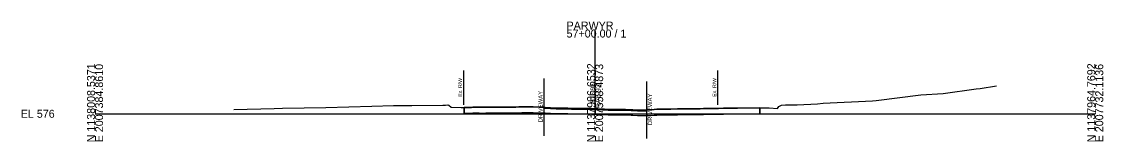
# Model space of a CAD drawing. Extents: x -2173 to 2007764, y -181 to 1138563.
# Drawn here: x 1017.4 to 1395.9, y 2490.3 to 2532.3 of the extents above; entities that cross this region are included whole.
import ezdxf

# ---------------------------------------------------------------- set-up
doc = ezdxf.new("R2010")
doc.units = 0
for name, color, linetype in [('Default', 7, 'Continuous'), ('RD_PD_Final_TrvlWay', 7, 'Continuous'), ('RD_PD_MedBWall', 7, 'Continuous'), ('RD_XS_ExPaveRet', 7, 'Continuous'), ('RD_XS_ExRW', 7, 'Continuous'), ('RD_XS_MedBWall', 7, 'Continuous'), ('RD_XS_SideStreet', 7, 'Continuous'), ('RD_XS_TX_Elev_EX', 7, 'Continuous'), ('RD_XS_TX_Elev_PR', 7, 'Continuous')]:
    doc.layers.add(name, color=color, linetype=linetype)

msp = doc.modelspace()

# ---------------------------------------------------------------- linework, layer by layer
at = {"layer": 'RD_PD_Final_TrvlWay'}
msp.add_lwpolyline([(1091.67, 2501.5), (1105.81, 2501.9), (1108.66, 2501.96), (1123.82, 2502.19), (1139.92, 2502.72), (1147.5, 2502.88), (1153.91, 2502.91), (1164.83, 2503.03), (1165.78, 2503.04), (1166.6, 2503.08), (1166.9, 2503.06), (1167.68, 2502.26), (1171.16, 2502.22), (1172.25, 2502.17), (1174.88, 2502.25), (1175.29, 2502.29), (1176.29, 2502.31), (1177.57, 2502.28), (1178.3, 2502.27), (1179.88, 2502.3), (1180.32, 2502.3), (1182.33, 2502.35), (1183.34, 2502.35), (1184.49, 2502.34), (1186.36, 2502.33), (1186.8, 2502.32), (1188.38, 2502.31), (1189.11, 2502.32), (1190.4, 2502.37), (1191.41, 2502.38), (1192.41, 2502.39), (1193.72, 2502.4), (1194.43, 2502.41), (1196.03, 2502.39), (1196.44, 2502.39), (1198.46, 2502.34), (1199.33, 2502.33), (1200.64, 2502.31), (1202.49, 2502.16), (1202.95, 2502.14), (1204.51, 2502.08), (1205.25, 2502.09), (1206.52, 2502.09), (1207.56, 2502.08), (1208.54, 2502.05), (1209.87, 2501.99), (1210.55, 2501.96), (1212.17, 2501.95), (1212.57, 2501.95), (1214.59, 2501.98), (1215.33, 2501.96), (1216.79, 2501.92), (1218.1, 2501.87), (1218.62, 2501.85), (1219.09, 2501.83), (1220.63, 2501.75), (1221.4, 2501.7), (1222.65, 2501.64), (1223.71, 2501.62), (1224.67, 2501.58), (1226.01, 2501.58), (1226.68, 2501.59), (1228.32, 2501.58), (1228.7, 2501.58), (1230.71, 2501.52), (1231.32, 2501.49), (1232.93, 2501.41), (1234.74, 2501.36), (1235.24, 2501.37), (1236.76, 2501.35), (1237.54, 2501.41), (1238.78, 2501.53), (1239.73, 2501.57), (1240.79, 2501.6), (1241.52, 2501.62), (1242.81, 2501.61), (1244.03, 2501.63), (1244.54, 2501.65), (1246.89, 2501.68), (1247.31, 2501.69), (1249.08, 2501.74), (1250.87, 2501.73), (1252.65, 2501.76), (1254.9, 2501.76), (1256, 2501.8), (1256.92, 2501.82), (1257.62, 2501.84), (1258.73, 2501.86), (1260.62, 2501.87), (1261.21, 2501.88), (1263, 2501.92), (1263.31, 2501.93), (1265.22, 2501.99), (1267, 2502.01), (1267.93, 2502.02), (1275.75, 2502.05), (1276.21, 2502.04), (1278.97, 2502.03), (1281.87, 2501.87), (1282.36, 2502.56), (1283.3, 2503.03), (1284.76, 2503.08), (1285.52, 2503.11), (1287.92, 2503.08), (1288.74, 2503.13), (1295.93, 2503.48), (1297.93, 2503.72), (1315.18, 2504.5), (1316.38, 2504.62), (1332.12, 2506.64), (1339.87, 2507.08), (1351.46, 2508.71), (1352.88, 2508.91), (1358.58, 2509.84)], dxfattribs=at)
at = {"layer": 'RD_PD_MedBWall'}
for p, q in [((1218.1, 2500), (1218.1, 2529.53)), ((1043.1, 2500), (1218.1, 2500)), ((1218.1, 2500), (1393.1, 2500))]:
    msp.add_line(p, q, dxfattribs=at)
at = {"layer": 'RD_XS_ExPaveRet'}
for p, q in [((1172.25, 2500.17), (1172.25, 2502.17)), ((1172.25, 2502.17), (1172.25, 2500.17)), ((1200.1, 2502.32), (1199.33, 2502.33)), ((1200.1, 2501.98), (1200.1, 2502.32)), ((1172.25, 2500.17), (1174.88, 2500.25)), ((1172.25, 2500.17), (1174.88, 2500.25)), ((1174.88, 2500.25), (1175.29, 2500.29)), ((1174.88, 2500.25), (1175.29, 2500.29)), ((1175.29, 2500.29), (1176.29, 2500.31)), ((1175.29, 2500.29), (1176.29, 2500.31)), ((1176.29, 2500.31), (1177.57, 2500.28)), ((1176.29, 2500.31), (1177.57, 2500.28)), ((1177.57, 2500.28), (1178.3, 2500.27)), ((1177.57, 2500.28), (1178.3, 2500.27)), ((1178.3, 2500.27), (1179.88, 2500.3)), ((1178.3, 2500.27), (1179.88, 2500.3)), ((1179.88, 2500.3), (1180.32, 2500.3)), ((1179.88, 2500.3), (1180.32, 2500.3)), ((1180.32, 2500.3), (1182.33, 2500.35)), ((1180.32, 2500.3), (1182.33, 2500.35)), ((1182.33, 2500.35), (1183.34, 2500.35)), ((1182.33, 2500.35), (1183.34, 2500.35)), ((1183.34, 2500.35), (1184.49, 2500.34)), ((1183.34, 2500.35), (1184.49, 2500.34)), ((1184.49, 2500.34), (1186.36, 2500.33)), ((1184.49, 2500.34), (1186.36, 2500.33)), ((1186.36, 2500.33), (1186.8, 2500.32)), ((1186.36, 2500.33), (1186.8, 2500.32)), ((1186.8, 2500.32), (1188.38, 2500.31)), ((1186.8, 2500.32), (1188.38, 2500.31)), ((1188.38, 2500.31), (1189.11, 2500.32)), ((1188.38, 2500.31), (1189.11, 2500.32)), ((1189.11, 2500.32), (1190.4, 2500.37)), ((1189.11, 2500.32), (1190.4, 2500.37)), ((1190.4, 2500.37), (1191.41, 2500.38)), ((1190.4, 2500.37), (1191.41, 2500.38)), ((1191.41, 2500.38), (1192.41, 2500.39)), ((1191.41, 2500.38), (1192.41, 2500.39)), ((1192.41, 2500.39), (1193.72, 2500.4)), ((1192.41, 2500.39), (1193.72, 2500.4)), ((1193.72, 2500.4), (1194.43, 2500.41)), ((1193.72, 2500.4), (1194.43, 2500.41)), ((1194.43, 2500.41), (1196.03, 2500.39)), ((1194.43, 2500.41), (1196.03, 2500.39)), ((1196.03, 2500.39), (1196.44, 2500.39)), ((1196.03, 2500.39), (1196.44, 2500.39)), ((1196.44, 2500.39), (1198.46, 2500.34)), ((1196.44, 2500.39), (1198.46, 2500.34)), ((1198.46, 2500.34), (1199.33, 2500.33)), ((1198.46, 2500.34), (1199.33, 2500.33)), ((1199.33, 2500.33), (1200.64, 2500.31)), ((1199.33, 2500.33), (1200.64, 2500.31)), ((1200.64, 2500.31), (1202.49, 2500.16)), ((1200.64, 2500.31), (1202.49, 2500.16)), ((1202.49, 2500.16), (1202.95, 2500.14)), ((1202.49, 2500.16), (1202.95, 2500.14)), ((1202.95, 2500.14), (1204.51, 2500.08)), ((1202.95, 2500.14), (1204.51, 2500.08)), ((1204.51, 2500.08), (1205.25, 2500.09)), ((1204.51, 2500.08), (1205.25, 2500.09)), ((1205.25, 2500.09), (1206.52, 2500.09)), ((1205.25, 2500.09), (1206.52, 2500.09)), ((1206.52, 2500.09), (1207.56, 2500.08)), ((1206.52, 2500.09), (1207.56, 2500.08)), ((1207.56, 2500.08), (1208.54, 2500.05)), ((1207.56, 2500.08), (1208.54, 2500.05)), ((1208.54, 2500.05), (1209.87, 2499.99)), ((1208.54, 2500.05), (1209.87, 2499.99)), ((1209.87, 2499.99), (1210.55, 2499.96)), ((1209.87, 2499.99), (1210.55, 2499.96)), ((1210.55, 2499.96), (1212.17, 2499.95)), ((1210.55, 2499.96), (1212.17, 2499.95)), ((1212.17, 2499.95), (1212.57, 2499.95)), ((1212.17, 2499.95), (1212.57, 2499.95)), ((1212.57, 2499.95), (1214.59, 2499.98)), ((1212.57, 2499.95), (1214.59, 2499.98)), ((1214.59, 2499.98), (1215.33, 2499.96)), ((1214.59, 2499.98), (1215.33, 2499.96)), ((1215.33, 2499.96), (1216.79, 2499.92)), ((1215.33, 2499.96), (1216.79, 2499.92)), ((1216.79, 2499.92), (1218.1, 2499.87)), ((1216.79, 2499.92), (1218.1, 2499.87)), ((1218.1, 2499.87), (1218.62, 2499.85)), ((1218.1, 2499.87), (1218.62, 2499.85)), ((1218.62, 2499.85), (1219.09, 2499.83)), ((1218.62, 2499.85), (1219.09, 2499.83)), ((1219.09, 2499.83), (1220.63, 2499.75)), ((1219.09, 2499.83), (1220.63, 2499.75)), ((1220.63, 2499.75), (1221.4, 2499.7)), ((1220.63, 2499.75), (1221.4, 2499.7)), ((1221.4, 2499.7), (1222.65, 2499.64)), ((1221.4, 2499.7), (1222.65, 2499.64)), ((1222.65, 2499.64), (1223.71, 2499.62)), ((1222.65, 2499.64), (1223.71, 2499.62)), ((1223.71, 2499.62), (1224.67, 2499.58)), ((1223.71, 2499.62), (1224.67, 2499.58)), ((1224.67, 2499.58), (1226.01, 2499.58)), ((1224.67, 2499.58), (1226.01, 2499.58)), ((1226.01, 2499.58), (1226.68, 2499.59)), ((1226.01, 2499.58), (1226.68, 2499.59)), ((1226.68, 2499.59), (1228.32, 2499.58)), ((1226.68, 2499.59), (1228.32, 2499.58)), ((1228.32, 2499.58), (1228.7, 2499.58)), ((1228.32, 2499.58), (1228.7, 2499.58)), ((1228.7, 2499.58), (1230.71, 2499.52)), ((1228.7, 2499.58), (1230.71, 2499.52)), ((1230.71, 2499.52), (1231.32, 2499.49)), ((1230.71, 2499.52), (1231.32, 2499.49)), ((1231.32, 2499.49), (1232.93, 2499.41)), ((1231.32, 2499.49), (1232.93, 2499.41)), ((1232.93, 2499.41), (1234.74, 2499.36)), ((1232.93, 2499.41), (1234.74, 2499.36)), ((1234.74, 2499.36), (1235.24, 2499.37)), ((1234.74, 2499.36), (1235.24, 2499.37)), ((1235.24, 2499.37), (1236.76, 2499.35)), ((1235.24, 2499.37), (1236.76, 2499.35)), ((1236.1, 2501.36), (1236.1, 2501.02)), ((1236.76, 2499.35), (1237.54, 2499.41)), ((1236.76, 2499.35), (1237.54, 2499.41)), ((1237.54, 2499.41), (1238.78, 2499.53)), ((1237.54, 2499.41), (1238.78, 2499.53)), ((1238.78, 2499.53), (1239.73, 2499.57)), ((1238.78, 2499.53), (1239.73, 2499.57)), ((1239.73, 2499.57), (1240.79, 2499.6)), ((1239.73, 2499.57), (1240.79, 2499.6)), ((1240.79, 2499.6), (1241.52, 2499.62)), ((1240.79, 2499.6), (1241.52, 2499.62)), ((1241.52, 2499.62), (1242.81, 2499.61)), ((1241.52, 2499.62), (1242.81, 2499.61)), ((1242.81, 2499.61), (1244.03, 2499.63)), ((1242.81, 2499.61), (1244.03, 2499.63)), ((1244.03, 2499.63), (1244.54, 2499.65)), ((1244.03, 2499.63), (1244.54, 2499.65)), ((1244.54, 2499.65), (1246.89, 2499.68)), ((1244.54, 2499.65), (1246.89, 2499.68)), ((1246.89, 2499.68), (1247.31, 2499.69)), ((1246.89, 2499.68), (1247.31, 2499.69)), ((1247.31, 2499.69), (1249.08, 2499.74)), ((1247.31, 2499.69), (1249.08, 2499.74)), ((1249.08, 2499.74), (1250.87, 2499.73)), ((1249.08, 2499.74), (1250.87, 2499.73)), ((1250.87, 2499.73), (1252.65, 2499.76)), ((1250.87, 2499.73), (1252.65, 2499.76)), ((1252.65, 2499.76), (1254.9, 2499.76)), ((1252.65, 2499.76), (1254.9, 2499.76)), ((1254.9, 2499.76), (1256, 2499.8)), ((1254.9, 2499.76), (1256, 2499.8)), ((1256, 2499.8), (1256.92, 2499.82)), ((1256, 2499.8), (1256.92, 2499.82)), ((1256.92, 2499.82), (1257.62, 2499.84)), ((1256.92, 2499.82), (1257.62, 2499.84)), ((1257.62, 2499.84), (1258.73, 2499.86)), ((1257.62, 2499.84), (1258.73, 2499.86)), ((1258.73, 2499.86), (1260.62, 2499.87)), ((1258.73, 2499.86), (1260.62, 2499.87)), ((1260.62, 2499.87), (1261.21, 2499.88)), ((1260.62, 2499.87), (1261.21, 2499.88)), ((1261.21, 2499.88), (1263, 2499.92)), ((1261.21, 2499.88), (1263, 2499.92)), ((1263, 2499.92), (1263.31, 2499.93)), ((1263, 2499.92), (1263.31, 2499.93)), ((1263.31, 2499.93), (1265.22, 2499.99)), ((1263.31, 2499.93), (1265.22, 2499.99)), ((1265.22, 2499.99), (1267, 2500.01)), ((1265.22, 2499.99), (1267, 2500.01)), ((1267, 2500.01), (1267.93, 2500.02)), ((1267, 2500.01), (1267.93, 2500.02)), ((1267.93, 2500.02), (1275.75, 2500.05)), ((1267.93, 2500.02), (1275.75, 2500.05)), ((1275.75, 2502.05), (1275.75, 2500.05)), ((1275.75, 2500.05), (1275.75, 2502.05))]:
    msp.add_line(p, q, dxfattribs=at)
for points in [[(1199.33, 2502.33), (1198.46, 2502.34), (1196.44, 2502.39), (1196.03, 2502.39), (1194.43, 2502.41), (1193.72, 2502.4), (1192.41, 2502.39), (1191.41, 2502.38), (1190.4, 2502.37), (1189.11, 2502.32), (1188.38, 2502.31), (1186.8, 2502.32), (1186.36, 2502.33), (1184.49, 2502.34), (1183.34, 2502.35), (1182.33, 2502.35), (1180.32, 2502.3), (1179.88, 2502.3), (1178.3, 2502.27), (1177.57, 2502.28), (1176.29, 2502.31), (1175.29, 2502.29), (1174.88, 2502.25), (1172.25, 2502.17)], [(1236.1, 2501.02), (1235.24, 2501.04), (1234.74, 2501.02), (1232.93, 2501.08), (1231.32, 2501.16), (1230.71, 2501.19), (1228.7, 2501.24), (1228.32, 2501.24), (1226.68, 2501.26), (1226.01, 2501.25), (1224.67, 2501.24), (1223.71, 2501.29), (1222.65, 2501.31), (1221.4, 2501.37), (1220.63, 2501.42), (1219.09, 2501.49), (1218.62, 2501.52), (1218.1, 2501.53), (1216.79, 2501.58), (1215.33, 2501.62), (1214.59, 2501.64), (1212.57, 2501.62), (1212.17, 2501.62), (1210.55, 2501.63), (1209.87, 2501.66), (1208.54, 2501.72), (1207.56, 2501.75), (1206.52, 2501.76), (1205.25, 2501.75), (1204.51, 2501.75), (1202.95, 2501.81), (1202.49, 2501.82), (1200.64, 2501.97), (1200.1, 2501.98)], [(1275.75, 2502.05), (1267.93, 2502.02), (1267, 2502.01), (1265.22, 2501.99), (1263.31, 2501.93), (1263, 2501.92), (1261.21, 2501.88), (1260.62, 2501.87), (1258.73, 2501.86), (1257.62, 2501.84), (1256.92, 2501.82), (1256, 2501.8), (1254.9, 2501.76), (1252.65, 2501.76), (1250.87, 2501.73), (1249.08, 2501.74), (1247.31, 2501.69), (1246.89, 2501.68), (1244.54, 2501.65), (1244.03, 2501.63), (1242.81, 2501.61), (1241.52, 2501.62), (1240.79, 2501.6), (1239.73, 2501.57), (1238.78, 2501.53), (1237.54, 2501.41), (1236.76, 2501.35), (1236.1, 2501.36)]]:
    msp.add_lwpolyline(points, dxfattribs=at)
at = {"layer": 'RD_XS_ExRW'}
for p, q in [((1171.98, 2515.17), (1171.98, 2503.17)), ((1260.97, 2515.17), (1260.97, 2503.17))]:
    msp.add_line(p, q, dxfattribs=at)
at = {"layer": 'RD_XS_MedBWall'}
for p, q in [((1200.1, 2502.32), (1200.1, 2501.98)), ((1236.1, 2501.36), (1236.1, 2501.02))]:
    msp.add_line(p, q, dxfattribs=at)
for points in [[(1200.1, 2502.32), (1200.64, 2502.31), (1202.49, 2502.16), (1202.95, 2502.14), (1204.51, 2502.08), (1205.25, 2502.09), (1206.52, 2502.09), (1207.56, 2502.08), (1208.54, 2502.05), (1209.87, 2501.99), (1210.55, 2501.96), (1212.17, 2501.95), (1212.57, 2501.95), (1214.59, 2501.98), (1215.33, 2501.96), (1216.79, 2501.92), (1218.1, 2501.87), (1218.62, 2501.85), (1219.09, 2501.83), (1220.63, 2501.75), (1221.4, 2501.7), (1222.65, 2501.64), (1223.71, 2501.62), (1224.67, 2501.58), (1226.01, 2501.58), (1226.68, 2501.59), (1228.32, 2501.58), (1228.7, 2501.58), (1230.71, 2501.52), (1231.32, 2501.49), (1232.93, 2501.41), (1234.74, 2501.36), (1235.24, 2501.37), (1236.1, 2501.36)], [(1200.1, 2501.98), (1200.64, 2501.97), (1202.49, 2501.82), (1202.95, 2501.81), (1204.51, 2501.75), (1205.25, 2501.75), (1206.52, 2501.76), (1207.56, 2501.75), (1208.54, 2501.72), (1209.87, 2501.66), (1210.55, 2501.63), (1212.17, 2501.62), (1212.57, 2501.62), (1214.59, 2501.64), (1215.33, 2501.62), (1216.79, 2501.58), (1218.1, 2501.53), (1218.62, 2501.52), (1219.09, 2501.49), (1220.63, 2501.42), (1221.4, 2501.37), (1222.65, 2501.31), (1223.71, 2501.29), (1224.67, 2501.24), (1226.01, 2501.25), (1226.68, 2501.26), (1228.32, 2501.24), (1228.7, 2501.24), (1230.71, 2501.19), (1231.32, 2501.16), (1232.93, 2501.08), (1234.74, 2501.02), (1235.24, 2501.04), (1236.1, 2501.02)]]:
    msp.add_lwpolyline(points, dxfattribs=at)
at = {"layer": 'RD_XS_SideStreet'}
for p, q in [((1200.1, 2512.32), (1200.1, 2492.32)), ((1236.1, 2511.36), (1236.1, 2491.36))]:
    msp.add_line(p, q, dxfattribs=at)

# ---------------------------------------------------------------- texts
at = {"layer": 'Default'}
msp.add_text('-', height=0.0001, dxfattribs=at).set_placement((1043.1, 2500))
at = {"layer": 'RD_PD_MedBWall'}
for s, p in [('57+00.00 / 1', (1208.1, 2526.73)), ('PARWYR', (1208.1, 2529.53)), ('EL 576', (1017.1, 2498.6))]:
    msp.add_text(s, height=2.8, dxfattribs=at).set_placement(p)
for s, p in [('N 1138008.5371', (1043.1, 2490)), ('E 2007384.8610', (1045.9, 2490)), ('N 1137986.6532', (1218.1, 2490)), ('E 2007558.4873', (1220.9, 2490)), ('N 1137964.7692', (1393.1, 2490)), ('E 2007732.1136', (1395.9, 2490))]:
    msp.add_text(s, height=2.8, rotation=90, dxfattribs=at).set_placement(p)
at = {"layer": 'RD_XS_ExRW'}
for p in [(1171.48, 2505.94), (1260.47, 2505.94)]:
    msp.add_text('Ex. R/W ', height=1.3, rotation=90, dxfattribs=at).set_placement(p)
at = {"layer": 'RD_XS_SideStreet'}
for p in [(1199.71, 2496.98), (1238.02, 2496.02)]:
    msp.add_text('DRIVEWAY', height=1.5, rotation=90, dxfattribs=at).set_placement(p)
at = {"layer": 'RD_XS_TX_Elev_EX'}
msp.add_text('576.93', height=1.6, rotation=90, dxfattribs=at).set_placement((1218, 2503.87))
at = {"layer": 'RD_XS_TX_Elev_PR'}
msp.add_text('576.93', height=1.8, rotation=90, dxfattribs=at).set_placement((1220, 2502.76))

doc.saveas('drawing.dxf')
